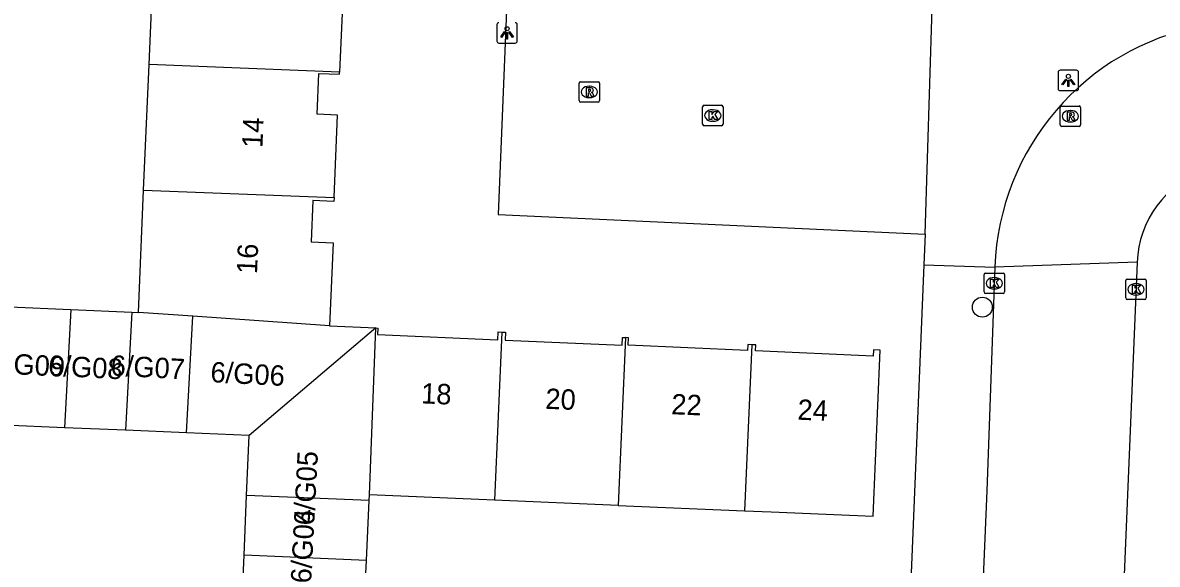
# Model space of a CAD drawing. Extents: x 160077 to 160945, y 386481 to 387498.
# Drawn here: x 160567 to 160622.7, y 386758.4 to 386784.9 of the extents above; entities that cross this region are included whole.
import ezdxf

# ---------------------------------------------------------------- set-up
doc = ezdxf.new("R2010")
doc.units = 0
for name, color, linetype in [('IMGEO_Boom', 7, 'Continuous'), ('IMGEO_Kolk', 7, 'Continuous'), ('IMGEO_Lichtpunt', 7, 'Continuous'), ('IMGEO_Pand', 7, 'Continuous'), ('IMGEO_Pand_nummerreeks', 7, 'Continuous'), ('IMGEO_Rijbaan_lokaal_open', 7, 'Continuous'), ('IMGEO_Rioolput', 7, 'Continuous'), ('IMGEO_Voetpad_open', 7, 'Continuous')]:
    doc.layers.add(name, color=color, linetype=linetype)

msp = doc.modelspace()

# ---------------------------------------------------------------- linework, layer by layer
at = {"layer": 'IMGEO_Boom'}
msp.add_circle((160614.071, 386770.994), 0.489, dxfattribs=at)
at = {"layer": 'IMGEO_Kolk'}
for p, q in [((160600.354, 386779.963), (160600.354, 386780.815)), ((160600.429, 386780.889), (160601.281, 386780.889)), ((160600.842, 386780.669), (160600.867, 386780.669)), ((160601.355, 386780.815), (160601.355, 386779.963)), ((160600.865, 386780.109), (160600.84, 386780.109)), ((160601.281, 386779.889), (160600.429, 386779.889)), ((160614.158, 386771.738), (160614.158, 386772.59)), ((160614.233, 386772.664), (160615.085, 386772.664)), ((160614.646, 386772.444), (160614.671, 386772.444)), ((160615.159, 386772.59), (160615.159, 386771.738)), ((160621.107, 386771.443), (160621.107, 386772.295)), ((160621.182, 386772.369), (160622.034, 386772.369)), ((160622.108, 386772.295), (160622.108, 386771.443)), ((160614.669, 386771.884), (160614.644, 386771.884)), ((160621.595, 386772.149), (160621.62, 386772.149)), ((160615.085, 386771.664), (160614.233, 386771.664)), ((160622.034, 386771.369), (160621.182, 386771.369)), ((160621.618, 386771.589), (160621.593, 386771.589))]:
    msp.add_line(p, q, dxfattribs=at)
for points in [[(160600.354, 386779.963), (160600.354, 386780.815)], [(160600.429, 386780.889), (160601.281, 386780.889)], [(160601.355, 386780.815), (160601.355, 386779.963)], [(160600.675, 386780.589), (160600.798, 386780.589), (160600.798, 386780.438), (160600.928, 386780.589), (160601.092, 386780.589), (160600.946, 386780.438), (160601.099, 386780.189), (160600.947, 386780.189), (160600.862, 386780.353), (160600.798, 386780.286), (160600.798, 386780.189), (160600.675, 386780.189), (160600.675, 386780.589)], [(160601.281, 386779.889), (160600.429, 386779.889)], [(160614.158, 386771.738), (160614.158, 386772.59)], [(160614.233, 386772.664), (160615.085, 386772.664)], [(160614.479, 386772.364), (160614.602, 386772.364), (160614.602, 386772.213), (160614.732, 386772.364), (160614.896, 386772.364), (160614.75, 386772.213), (160614.903, 386771.964), (160614.751, 386771.964), (160614.666, 386772.128), (160614.602, 386772.061), (160614.602, 386771.964), (160614.479, 386771.964), (160614.479, 386772.364)], [(160615.159, 386772.59), (160615.159, 386771.738)], [(160621.107, 386771.443), (160621.107, 386772.295)], [(160621.182, 386772.369), (160622.034, 386772.369)], [(160622.108, 386772.295), (160622.108, 386771.443)], [(160621.428, 386772.069), (160621.551, 386772.069), (160621.551, 386771.918), (160621.681, 386772.069), (160621.845, 386772.069), (160621.699, 386771.918), (160621.852, 386771.669), (160621.7, 386771.669), (160621.615, 386771.833), (160621.551, 386771.766), (160621.551, 386771.669), (160621.428, 386771.669), (160621.428, 386772.069)], [(160615.085, 386771.664), (160614.233, 386771.664)], [(160622.034, 386771.369), (160621.182, 386771.369)]]:
    msp.add_lwpolyline(points, dxfattribs=at)
for centre, start, end in [((160600.431, 386780.813), 91.552, 178.448), ((160600.431, 386780.813), 91.552, 178.448), ((160601.279, 386780.813), 1.552, 88.448), ((160601.279, 386780.813), 1.552, 88.448), ((160600.431, 386779.965), 181.552, 268.448), ((160600.431, 386779.965), 181.552, 268.448), ((160601.279, 386779.965), 271.552, 358.448), ((160601.279, 386779.965), 271.552, 358.448), ((160614.235, 386772.588), 91.552, 178.448), ((160614.235, 386772.588), 91.552, 178.448), ((160615.083, 386772.588), 1.552, 88.448), ((160615.083, 386772.588), 1.552, 88.448), ((160621.184, 386772.293), 91.552, 178.448), ((160621.184, 386772.293), 91.552, 178.448), ((160622.032, 386772.293), 1.552, 88.448), ((160622.032, 386772.293), 1.552, 88.448), ((160614.235, 386771.74), 181.552, 268.448), ((160614.235, 386771.74), 181.552, 268.448), ((160615.083, 386771.74), 271.552, 358.448), ((160615.083, 386771.74), 271.552, 358.448), ((160621.184, 386771.445), 181.552, 268.448), ((160621.184, 386771.445), 181.552, 268.448), ((160622.032, 386771.445), 271.552, 358.448), ((160622.032, 386771.445), 271.552, 358.448)]:
    msp.add_arc(centre, 0.0765, start, end, dxfattribs=at)
for centre, major_axis, ratio, start_param, end_param in [((160600.841, 386780.389), (-0.387, 0.002), 0.722429, 4.712389, 7.853982), ((160600.866, 386780.389), (-0.39, 0.002), 0.717154, 1.570796, 4.712389), ((160614.645, 386772.164), (-0.387, 0.002), 0.722429, 4.712389, 7.853982), ((160614.67, 386772.164), (-0.39, 0.002), 0.717154, 1.570796, 4.712389), ((160621.594, 386771.869), (-0.387, 0.002), 0.722429, 4.712389, 7.853982), ((160621.619, 386771.869), (-0.39, 0.002), 0.717154, 1.570796, 4.712389)]:
    msp.add_ellipse(centre, major_axis=major_axis, ratio=ratio, start_param=start_param, end_param=end_param, dxfattribs=at)
at = {"layer": 'IMGEO_Lichtpunt'}
for p, q in [((160590.264, 386784.844), (160590.264, 386784.037)), ((160590.264, 386784.844), (160590.264, 386784.037)), ((160591.26, 386784.037), (160591.26, 386784.844)), ((160591.26, 386784.037), (160591.26, 386784.844)), ((160590.358, 386783.943), (160591.166, 386783.943)), ((160590.358, 386783.943), (160591.166, 386783.943)), ((160617.791, 386782.513), (160617.791, 386781.706)), ((160617.791, 386782.513), (160617.791, 386781.706)), ((160618.693, 386782.608), (160617.885, 386782.608)), ((160618.693, 386782.608), (160617.885, 386782.608)), ((160618.787, 386781.706), (160618.787, 386782.513)), ((160618.787, 386781.706), (160618.787, 386782.513)), ((160617.885, 386781.612), (160618.693, 386781.612)), ((160617.885, 386781.612), (160618.693, 386781.612))]:
    msp.add_line(p, q, dxfattribs=at)
for points in [[(160590.638, 386784.508), (160590.677, 386784.48), (160590.489, 386784.218), (160590.451, 386784.245), (160590.638, 386784.508)], [(160590.74, 386784.46), (160590.787, 386784.46), (160590.787, 386784.138), (160590.74, 386784.138), (160590.74, 386784.46)], [(160590.85, 386784.48), (160590.888, 386784.507), (160591.075, 386784.245), (160591.036, 386784.217), (160590.85, 386784.48)], [(160618.165, 386782.177), (160618.204, 386782.149), (160618.016, 386781.887), (160617.978, 386781.914), (160618.165, 386782.177)], [(160618.267, 386782.129), (160618.314, 386782.129), (160618.314, 386781.807), (160618.267, 386781.807), (160618.267, 386782.129)], [(160618.377, 386782.149), (160618.415, 386782.176), (160618.602, 386781.914), (160618.563, 386781.886), (160618.377, 386782.149)]]:
    msp.add_lwpolyline(points, dxfattribs=at)
for centre in [(160590.763, 386784.642), (160618.29, 386782.311)]:
    msp.add_circle(centre, 0.0994, dxfattribs=at)
for centre, start, end in [((160590.358, 386784.844), 90, 180), ((160590.358, 386784.844), 90, 180), ((160591.166, 386784.844), 0, 90), ((160591.166, 386784.844), 0, 90), ((160590.358, 386784.037), 180, 270), ((160590.358, 386784.037), 180, 270), ((160591.166, 386784.037), 270, 0), ((160591.166, 386784.037), 270, 360), ((160617.885, 386782.513), 90, 180), ((160617.885, 386782.513), 90, 180), ((160618.693, 386782.513), 0, 90), ((160618.693, 386782.513), 0, 90), ((160617.885, 386781.706), 180, 270), ((160617.885, 386781.706), 180, 270), ((160618.693, 386781.706), 270, 0), ((160618.693, 386781.706), 270, 360)]:
    msp.add_arc(centre, 0.0946, start, end, dxfattribs=at)
at = {"layer": 'IMGEO_Pand'}
for points in [[(160573.205, 386782.883), (160573.468, 386789.029)], [(160582.853, 386788.657), (160582.847, 386788.514), (160581.769, 386788.56), (160581.682, 386786.55), (160582.725, 386786.505), (160582.553, 386782.512)], [(160572.941, 386776.737), (160573.205, 386782.883)], [(160582.553, 386782.512), (160573.205, 386782.883)], [(160582.282, 386776.367), (160582.455, 386780.414), (160581.443, 386780.457), (160581.529, 386782.455), (160582.549, 386782.411), (160582.553, 386782.512)], [(160572.684, 386770.735), (160572.941, 386776.737)], [(160572.941, 386776.737), (160582.282, 386776.367)], [(160582.282, 386776.367), (160582.274, 386776.179), (160581.237, 386776.223), (160581.15, 386774.193), (160582.235, 386774.146), (160582.06, 386770.072)], [(160566.383, 386771.005), (160569.377, 386770.877)], [(160569.377, 386770.877), (160569.056, 386765.084)], [(160569.377, 386770.877), (160572.37, 386770.748)], [(160572.37, 386770.748), (160572.049, 386764.956)], [(160572.37, 386770.748), (160572.684, 386770.735)], [(160575.359, 386770.546), (160572.684, 386770.735)], [(160575.043, 386764.828), (160575.359, 386770.546)], [(160582.06, 386770.072), (160575.359, 386770.546)], [(160582.06, 386770.072), (160584.329, 386769.974)], [(160584.329, 386769.974), (160578.119, 386764.696)], [(160584.017, 386761.798), (160584.329, 386769.974)], [(160584.329, 386769.974), (160584.429, 386769.97), (160584.416, 386769.653), (160590.308, 386769.4), (160590.325, 386769.779), (160590.502, 386769.772)], [(160590.502, 386769.772), (160590.148, 386761.536)], [(160590.502, 386769.772), (160590.682, 386769.764), (160590.665, 386769.376), (160596.414, 386769.129), (160596.43, 386769.506), (160596.572, 386769.5)], [(160596.572, 386769.5), (160596.218, 386761.276)], [(160602.765, 386769.154), (160602.566, 386769.162), (160602.553, 386768.872), (160596.698, 386769.123), (160596.714, 386769.494), (160596.572, 386769.5)], [(160602.415, 386761.011), (160603.719, 386760.955), (160608.713, 386760.741), (160609.062, 386768.883), (160608.732, 386768.897), (160608.719, 386768.599), (160602.953, 386768.847), (160602.966, 386769.145), (160602.765, 386769.154)], [(160602.765, 386769.154), (160602.415, 386761.011)], [(160569.056, 386765.084), (160566.063, 386765.213)], [(160572.049, 386764.956), (160569.056, 386765.084)], [(160575.043, 386764.828), (160572.049, 386764.956)], [(160578.119, 386764.696), (160575.043, 386764.828)], [(160577.993, 386761.767), (160578.119, 386764.696)], [(160577.868, 386758.838), (160577.993, 386761.767)], [(160584.003, 386761.509), (160577.993, 386761.767)], [(160584.003, 386761.509), (160584.017, 386761.798)], [(160590.148, 386761.536), (160584.017, 386761.798)], [(160583.864, 386758.58), (160584.003, 386761.509)], [(160596.218, 386761.276), (160590.148, 386761.536)], [(160596.218, 386761.276), (160602.415, 386761.011)], [(160577.742, 386755.908), (160577.868, 386758.838)], [(160583.864, 386758.58), (160577.868, 386758.838)], [(160583.725, 386755.652), (160583.864, 386758.58)]]:
    msp.add_lwpolyline(points, dxfattribs=at)
at = {"layer": 'IMGEO_Rijbaan_lokaal_open'}
for points in [[(160614.688, 386772.962), (160614.299, 386761.99), (160613.792, 386750), (160613.446, 386741.825), (160612.561, 386721.068)], [(160621.661, 386773.193), (160614.688, 386772.962)], [(160621.661, 386773.193), (160620.706, 386750), (160620.278, 386739.623), (160619.524, 386720.686)]]:
    msp.add_lwpolyline(points, dxfattribs=at)
for centre, radius, start, end in [((160627.149, 386772.519), 12.469, 100.7335, 177.9641), ((160626.665, 386772.989), 5.009, 109.7003, 177.6611)]:
    msp.add_arc(centre, radius, start, end, dxfattribs=at)
at = {"layer": 'IMGEO_Rioolput'}
for p, q in [((160594.298, 386781.119), (160594.298, 386781.971)), ((160594.373, 386782.045), (160595.225, 386782.045)), ((160594.786, 386781.825), (160594.811, 386781.825)), ((160595.299, 386781.971), (160595.299, 386781.119)), ((160594.809, 386781.265), (160594.784, 386781.265)), ((160595.225, 386781.045), (160594.373, 386781.045)), ((160617.888, 386779.929), (160617.888, 386780.781)), ((160617.963, 386780.855), (160618.815, 386780.855)), ((160618.889, 386780.781), (160618.889, 386779.929)), ((160618.376, 386780.635), (160618.401, 386780.635)), ((160618.815, 386779.855), (160617.963, 386779.855)), ((160618.399, 386780.075), (160618.374, 386780.075))]:
    msp.add_line(p, q, dxfattribs=at)
for points in [[(160594.298, 386781.119), (160594.298, 386781.971)], [(160594.373, 386782.045), (160595.225, 386782.045)], [(160595.299, 386781.971), (160595.299, 386781.119)], [(160594.887, 386781.743), (160594.635, 386781.745), (160594.635, 386781.345)], [(160594.635, 386781.345), (160594.759, 386781.345), (160594.759, 386781.507), (160594.77, 386781.507)], [(160594.813, 386781.664), (160594.759, 386781.664), (160594.759, 386781.583)], [(160594.759, 386781.583), (160594.811, 386781.583)], [(160594.817, 386781.478), (160594.888, 386781.345), (160595.028, 386781.345), (160594.963, 386781.471)], [(160595.225, 386781.045), (160594.373, 386781.045)], [(160617.888, 386779.929), (160617.888, 386780.781)], [(160617.963, 386780.855), (160618.815, 386780.855)], [(160618.889, 386780.781), (160618.889, 386779.929)], [(160618.477, 386780.553), (160618.225, 386780.555), (160618.225, 386780.155)], [(160618.225, 386780.155), (160618.349, 386780.155), (160618.349, 386780.317), (160618.36, 386780.317)], [(160618.403, 386780.474), (160618.349, 386780.474), (160618.349, 386780.393)], [(160618.349, 386780.393), (160618.401, 386780.393)], [(160618.407, 386780.288), (160618.478, 386780.155), (160618.618, 386780.155), (160618.553, 386780.281)], [(160618.815, 386779.855), (160617.963, 386779.855)]]:
    msp.add_lwpolyline(points, dxfattribs=at)
for centre, radius, start, end in [((160594.375, 386781.969), 0.0765, 91.552, 178.448), ((160594.375, 386781.969), 0.0765, 91.552, 178.448), ((160595.223, 386781.969), 0.0765, 1.552, 88.448), ((160595.223, 386781.969), 0.0765, 1.552, 88.448), ((160594.769, 386781.454), 0.0533, 26.0293, 88.6989), ((160594.795, 386781.772), 0.19, 274.7715, 282.9687), ((160594.819, 386781.568), 0.0964, 77.0061, 93.1865), ((160594.833, 386781.625), 0.0378, 276.6634, 79.6772), ((160594.886, 386781.633), 0.109, 350.3612, 89.416), ((160594.884, 386781.633), 0.112, 277.5842, 350.9817), ((160594.868, 386781.418), 0.108, 29.5134, 73.7905), ((160594.375, 386781.121), 0.0765, 181.552, 268.448), ((160594.375, 386781.121), 0.0765, 181.552, 268.448), ((160595.223, 386781.121), 0.0765, 271.552, 358.448), ((160595.223, 386781.121), 0.0765, 271.552, 358.448), ((160617.965, 386780.779), 0.0765, 91.552, 178.448), ((160617.965, 386780.779), 0.0765, 91.552, 178.448), ((160618.813, 386780.779), 0.0765, 1.552, 88.448), ((160618.813, 386780.779), 0.0765, 1.552, 88.448), ((160618.359, 386780.264), 0.0533, 26.0293, 88.6989), ((160618.385, 386780.582), 0.19, 274.7715, 282.9687), ((160618.409, 386780.378), 0.0964, 77.0061, 93.1865), ((160618.423, 386780.435), 0.0378, 276.6634, 79.6772), ((160618.476, 386780.443), 0.109, 350.3612, 89.416), ((160618.474, 386780.443), 0.112, 277.5842, 350.9817), ((160618.458, 386780.228), 0.108, 29.5134, 73.7905), ((160617.965, 386779.931), 0.0765, 181.552, 268.448), ((160617.965, 386779.931), 0.0765, 181.552, 268.448), ((160618.813, 386779.931), 0.0765, 271.552, 358.448), ((160618.813, 386779.931), 0.0765, 271.552, 358.448)]:
    msp.add_arc(centre, radius, start, end, dxfattribs=at)
for centre, major_axis, ratio, start_param, end_param in [((160594.785, 386781.545), (-0.387, 0.002), 0.722429, 4.712389, 7.853982), ((160594.81, 386781.545), (-0.39, 0.002), 0.717154, 1.570796, 4.712389), ((160618.375, 386780.355), (-0.387, 0.002), 0.722429, 4.712389, 7.853982), ((160618.4, 386780.355), (-0.39, 0.002), 0.717154, 1.570796, 4.712389)]:
    msp.add_ellipse(centre, major_axis=major_axis, ratio=ratio, start_param=start_param, end_param=end_param, dxfattribs=at)
at = {"layer": 'IMGEO_Voetpad_open'}
for points in [[(160592.101, 386819.194), (160590.331, 386775.537), (160611.261, 386774.569)], [(160611.261, 386774.569), (160611.61, 386785.659)], [(160611.261, 386774.569), (160611.199, 386773.064)], [(160611.199, 386773.064), (160610.255, 386750), (160610.202, 386748.699)], [(160611.199, 386773.064), (160614.688, 386772.962)]]:
    msp.add_lwpolyline(points, dxfattribs=at)

# ---------------------------------------------------------------- texts
at = {"layer": 'IMGEO_Pand_nummerreeks'}
for s, rotation, p in [('14', 87.5592, (160578.764, 386778.785)), ('16', 87.5592, (160578.5, 386772.605)), ('6/G09', 356.957, (160565.422, 386767.769)), ('6/G08', 356.957, (160568.245, 386767.646)), ('6/G07', 356.957, (160571.302, 386767.647)), ('6/G06', 356.957, (160576.2, 386767.32)), ('18', 357.5171, (160586.533, 386766.279)), ('20', 357.5171, (160592.626, 386766.014)), ('22', 357.5171, (160598.803, 386765.747)), ('24', 357.5171, (160604.99, 386765.479)), ('6/G05', 86.957, (160581.3, 386760.277)), ('6/G04', 86.957, (160581.149, 386757.436))]:
    msp.add_text(s, height=1, rotation=rotation, dxfattribs=at).set_placement(p)

doc.saveas('drawing.dxf')
